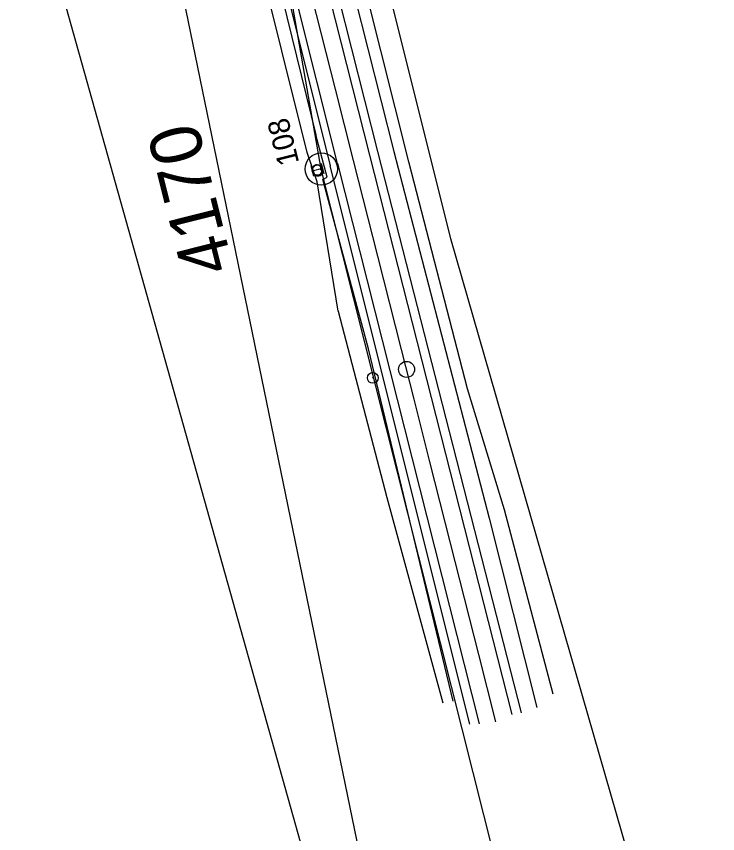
# Model space of a CAD drawing. Extents: x -754679 to -754173, y -1169241 to -1168288.
# Drawn here: x -754523.8 to -754458.2, y -1168596.9 to -1168520.4 of the extents above; entities that cross this region are included whole.
import ezdxf

# ---------------------------------------------------------------- set-up
doc = ezdxf.new("R2010")
doc.units = 0
for name, color, linetype in [('Vrstva 1', 7, 'Continuous'), ('Vrstva 11', 7, 'Continuous'), ('Vrstva 12', 7, 'Continuous'), ('Vrstva 16', 7, 'Continuous'), ('Vrstva 2', 7, 'Continuous'), ('Vrstva 4', 7, 'Continuous'), ('Vrstva 53', 7, 'Continuous'), ('Vrstva 55', 7, 'Continuous'), ('Vrstva 63', 7, 'Continuous'), ('Vrstva 7', 7, 'Continuous')]:
    doc.layers.add(name, color=color, linetype=linetype)

msp = doc.modelspace()

# ---------------------------------------------------------------- linework, layer by layer
at = {"layer": 'Vrstva 1'}
msp.add_line((-754495.294, -1168534.725), (-754495.294, -1168534.725), dxfattribs=at)
msp.add_lwpolyline([(-754478.966, -1168586.464), (-754480.559, -1168580.169), (-754482.76, -1168571.467), (-754485.127, -1168562.116), (-754486.611, -1168556.258), (-754487.789, -1168551.609), (-754490.001, -1168542.893), (-754492.27, -1168533.933), (-754493.964, -1168527.245), (-754496.176, -1168518.505), (-754498.393, -1168509.746)], dxfattribs=at)
at = {"layer": 'Vrstva 11'}
for p, q in [((-754496.27, -1168534.438), (-754496.025, -1168535.407)), ((-754495.178, -1168534.678), (-754496.148, -1168534.922)), ((-754495.301, -1168534.193), (-754495.056, -1168535.162))]:
    msp.add_line(p, q, dxfattribs=at)
at = {"layer": 'Vrstva 12'}
for p, q in [((-754495.81, -1168534.343), (-754495.802, -1168534.381)), ((-754495.23, -1168534.709), (-754495.157, -1168534.698)), ((-754496.116, -1168534.911), (-754496.172, -1168534.906)), ((-754495.499, -1168535.256), (-754495.53, -1168535.37))]:
    msp.add_line(p, q, dxfattribs=at)
for centre, major_axis, ratio, start_param, end_param in [((-754495.64, -1168534.85), (0.46, -0.299), 0.939519, 2.440374, 5.467649), ((-754495.661, -1168534.822), (0.313, -0.341), 0.999908, 2.707105, 5.898813), ((-754495.669, -1168534.856), (-0.496, 0.233), 0.95292, 2.24933, 5.396238), ((-754495.678, -1168534.828), (-0.307, 0.348), 0.999899, 2.814721, 5.829233)]:
    msp.add_ellipse(centre, major_axis=major_axis, ratio=ratio, start_param=start_param, end_param=end_param, dxfattribs=at)
at = {"layer": 'Vrstva 16'}
for p, q in [((-754487.095, -1168534.063), (-754494.989, -1168502.631)), ((-754496.017, -1168503.323), (-754488.517, -1168533.073)), ((-754502.477, -1168504.38), (-754495.806, -1168531.515)), ((-754493.73, -1168548.019), (-754495.689, -1168535.919)), ((-754490.872, -1168551.556), (-754495.142, -1168535.719)), ((-754482.938, -1168584.518), (-754490.872, -1168551.556))]:
    msp.add_line(p, q, dxfattribs=at)
for points in [[(-754495.689, -1168535.919), (-754496.618, -1168533.182), (-754503.69, -1168504.738)], [(-754495.142, -1168535.719), (-754494.753, -1168535.494), (-754495.806, -1168531.515)], [(-754488.517, -1168533.073), (-754479.582, -1168567.393), (-754475.116, -1168585.128)], [(-754473.582, -1168583.879), (-754478.136, -1168566.619), (-754481.613, -1168555.301), (-754487.095, -1168534.063)], [(-754493.73, -1168548.019), (-754489.172, -1168565.462), (-754483.916, -1168584.676)]]:
    msp.add_lwpolyline(points, dxfattribs=at)
at = {"layer": 'Vrstva 4'}
for p, q in [((-754493.778, -1168534.213), (-754501.317, -1168504.203)), ((-754498.341, -1168503.657), (-754490.791, -1168533.412)), ((-754490.002, -1168533.075), (-754497.491, -1168503.468)), ((-754501.987, -1168504.305), (-754494.473, -1168534.435)), ((-754476.542, -1168585.617), (-754490.002, -1168533.075)), ((-754490.791, -1168533.412), (-754477.468, -1168585.787)), ((-754481.398, -1168586.69), (-754494.473, -1168534.435)), ((-754493.778, -1168534.213), (-754480.524, -1168586.638))]:
    msp.add_line(p, q, dxfattribs=at)
at = {"layer": 'Vrstva 53'}
for p, q in [((-754494.84, -1168494.63), (-754483.21, -1168541.23)), ((-754490.14, -1168623.07), (-754523.85, -1168502.96)), ((-754483.21, -1168541.23), (-754460.6, -1168619.67))]:
    msp.add_line(p, q, dxfattribs=at)
at = {"layer": 'Vrstva 55'}
msp.add_line((-754486.32, -1168624.94), (-754519.8, -1168462.41), dxfattribs=at)
at = {"layer": 'Vrstva 63'}
msp.add_line((-754495.394, -1168534.725), (-754495.194, -1168534.725), dxfattribs=at)
msp.add_lwpolyline([(-754454.675, -1168695.978), (-754495.294, -1168534.725), (-754520.586, -1168389.665)], dxfattribs=at)
msp.add_circle((-754495.294, -1168534.725), 1.512, dxfattribs=at)
at = {"layer": 'Vrstva 7'}
msp.add_line((-754490.43, -1168554.263), (-754490.526, -1168554.289), dxfattribs=at)
for centre, radius in [((-754487.316, -1168553.475), 0.75), ((-754490.478, -1168554.276), 0.5)]:
    msp.add_circle(centre, radius, dxfattribs=at)

# ---------------------------------------------------------------- texts
at = {"layer": 'Vrstva 11'}
msp.add_text('108', height=2, rotation=104.17688, dxfattribs=at).set_placement((-754497.353, -1168534.128))
at = {"layer": 'Vrstva 2'}
msp.add_text('4170', height=4.8, rotation=104.13845, dxfattribs=at).set_placement((-754503.5, -1168543.992))

doc.saveas('drawing.dxf')
